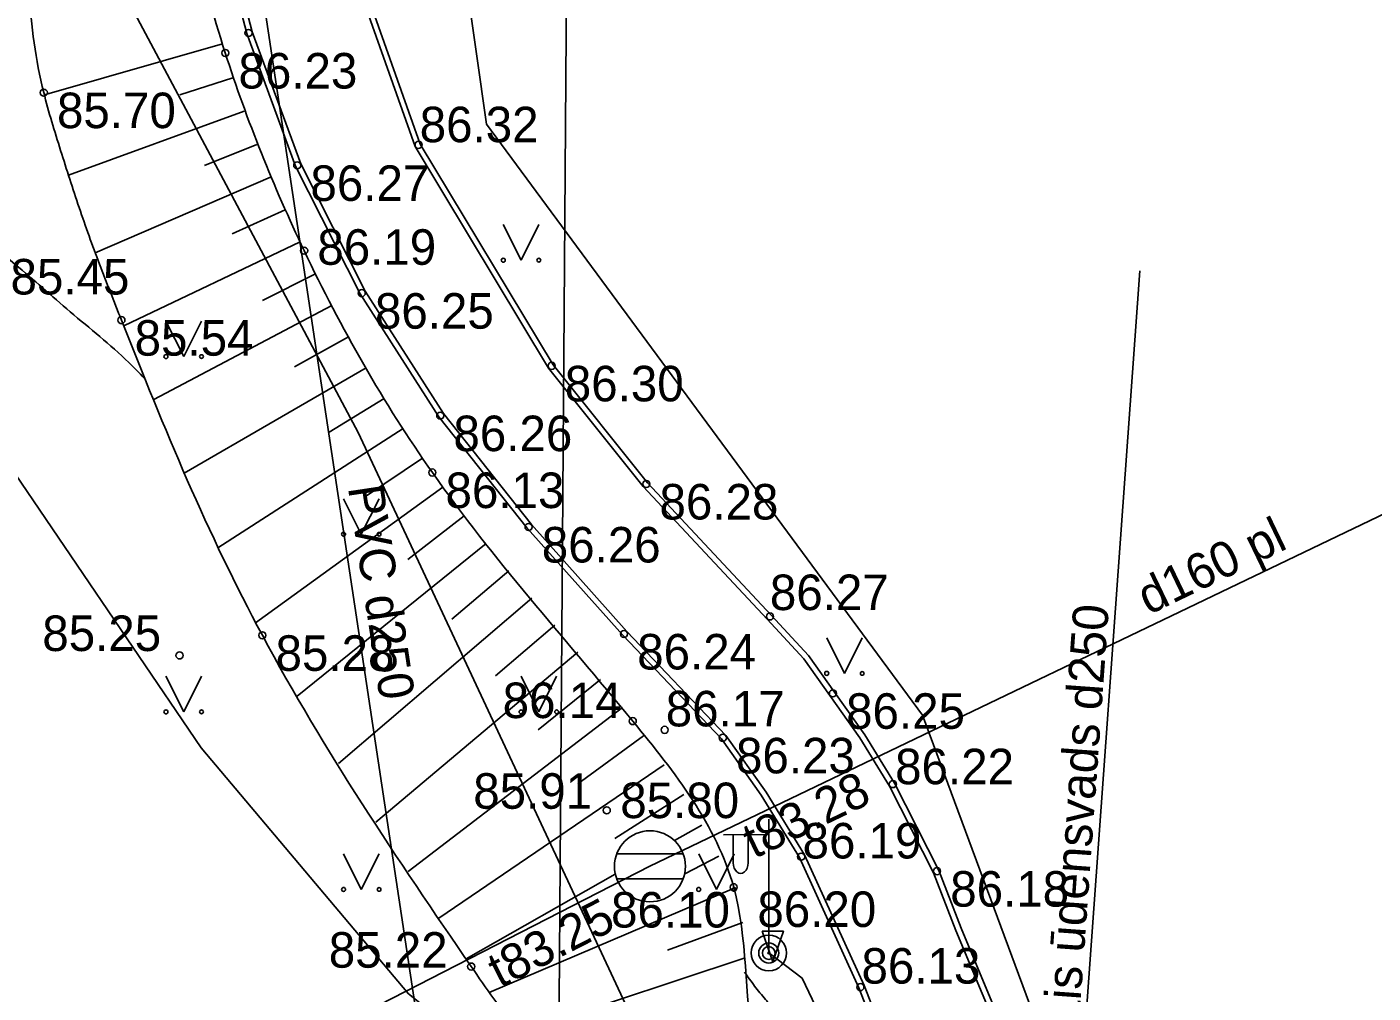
# Model space of a CAD drawing. Extents: x 576692 to 577659, y 273254 to 273799.
# Drawn here: x 576860.29 to 576879.24, y 273628.54 to 273642.14 of the extents above; entities that cross this region are included whole.
import ezdxf

# ---------------------------------------------------------------- set-up
doc = ezdxf.new("R2010")
doc.units = 0
for name, color, linetype in [('BUVE_EKAS_####_####_#', 7, 'Continuous'), ('CELI_TAKA_####_####_#', 7, 'Continuous'), ('GAZE_ELEM_####_####_#', 7, 'Continuous'), ('GEOD_ELEM_####_TKST_#', 7, 'Continuous'), ('GEOD_SITP_####_TKST_#', 7, 'Continuous'), ('HIDT_REZV_####_TKST_#', 7, 'Continuous'), ('Level 46', 7, 'Continuous'), ('Level 50', 7, 'Continuous'), ('LKAN_ELEM_####_####_#', 7, 'Continuous'), ('LKAN_ELEM_PAST_TKST_#', 7, 'Continuous'), ('RELJ_ELEM_####_####_#', 7, 'Continuous'), ('SAKK_KKAN_####_####_#', 7, 'Continuous'), ('SAKT_ACRL_####_####_#', 7, 'Continuous'), ('SAKT_ELEM_####_####_#', 7, 'Continuous'), ('SILT_VADP_DREN_TKST_#', 7, 'Continuous'), ('SILT_VADP_UDEN_####_#', 7, 'Continuous'), ('TERT_DIAM_####_TKST_#', 7, 'Continuous'), ('TERT_IZMT_####_TKST_#', 7, 'Continuous'), ('TERT_KONT_####_####_#', 7, 'Continuous'), ('TERT_KRND_####_####_#', 7, 'Continuous'), ('UDTK_VADP_UDEN_####_#', 7, 'Continuous')]:
    doc.layers.add(name, color=color, linetype=linetype)

msp = doc.modelspace()

# ---------------------------------------------------------------- linework, layer by layer
at = {"layer": 'BUVE_EKAS_####_####_#'}
for points in [[(576862.868, 273644.043), (576863.388, 273642.048), (576864.075, 273640.181), (576864.984, 273638.381), (576866.091, 273636.654), (576867.336, 273635.086), (576868.68, 273633.579), (576870.07, 273632.118), (576870.631, 273631.326), (576871.17, 273630.449), (576872.003, 273628.616), (576872.737, 273626.741), (576873.428, 273624.858), (576873.73, 273623.183), (576873.839, 273621.55), (576873.82, 273620.221), (576873.816, 273617.847)], [(576862.946, 273644.061), (576863.465, 273642.071), (576864.149, 273640.213), (576865.054, 273638.42), (576866.156, 273636.701), (576867.397, 273635.137), (576868.738, 273633.633), (576870.132, 273632.169), (576870.698, 273631.37), (576871.241, 273630.487), (576872.077, 273628.647), (576872.811, 273626.769), (576873.505, 273624.879), (576873.81, 273623.193), (576873.919, 273621.552), (576873.9, 273620.221), (576873.896, 273617.847)], [(576864.529, 273643.93), (576865.756, 273640.457), (576867.634, 273637.338), (576868.97, 273635.671), (576870.713, 273633.806), (576871.231, 273633.244), (576871.594, 273632.729), (576872.019, 273632.132), (576872.435, 273631.456), (576873.055, 273630.236), (576873.369, 273629.423), (576873.871, 273628.221), (576874.788, 273625.782), (576875.095, 273624.75), (576875.259, 273623.935), (576875.408, 273622.331), (576875.42, 273620.146), (576875.418, 273618.062), (576875.379, 273612.665)], [(576864.606, 273643.951), (576865.829, 273640.492), (576867.7, 273637.384), (576869.031, 273635.723), (576870.771, 273633.86), (576871.293, 273633.295), (576871.659, 273632.775), (576872.086, 273632.176), (576872.505, 273631.495), (576873.128, 273630.268), (576873.443, 273629.453), (576873.945, 273628.25), (576874.864, 273625.808), (576875.172, 273624.769), (576875.338, 273623.947), (576875.488, 273622.335), (576875.5, 273620.146), (576875.498, 273618.062), (576875.459, 273612.665)]]:
    msp.add_lwpolyline(points, dxfattribs=at)
at = {"layer": 'CELI_TAKA_####_####_#'}
msp.add_lwpolyline([(576822.461, 273734.186), (576841.308, 273671.168), (576850.453, 273673.856), (576864.919, 273653.745), (576866.76, 273640.771), (576872.899, 273632.451), (576876.069, 273623.909), (576875.901, 273608.92), (576873.238, 273590.115)], dxfattribs=at)
at = {"layer": 'GAZE_ELEM_####_####_#'}
for p, q in [((576863.048, 273641.904), (576860.538, 273641.186)), ((576863.191, 273641.425), (576862.443, 273641.185)), ((576863.353, 273640.952), (576860.877, 273640.052)), ((576863.531, 273640.484), (576862.79, 273640.19)), ((576863.723, 273640.023), (576861.254, 273638.961)), ((576863.926, 273639.566), (576863.184, 273639.227)), ((576864.137, 273639.113), (576861.656, 273637.932)), ((576864.355, 273638.663), (576863.608, 273638.29)), ((576864.583, 273638.217), (576862.077, 273636.896)), ((576864.82, 273637.777), (576864.061, 273637.358)), ((576865.066, 273637.342), (576862.508, 273635.86)), ((576865.322, 273636.912), (576864.547, 273636.438)), ((576865.587, 273636.489), (576862.978, 273634.81)), ((576865.862, 273636.071), (576865.071, 273635.54)), ((576866.147, 273635.66), (576863.51, 273633.755)), ((576866.446, 273635.259), (576865.655, 273634.646)), ((576866.757, 273634.868), (576864.099, 273632.721)), ((576867.075, 273634.483), (576866.272, 273633.806)), ((576867.399, 273634.101), (576864.677, 273631.774)), ((576867.724, 273633.721), (576866.891, 273633.009)), ((576868.047, 273633.34), (576865.206, 273630.946)), ((576868.366, 273632.954), (576867.488, 273632.245)), ((576868.676, 273632.562), (576865.659, 273630.253)), ((576868.974, 273632.161), (576868.048, 273631.485)), ((576869.263, 273631.753), (576866.093, 273629.598)), ((576869.538, 273631.335), (576868.568, 273630.719)), ((576869.796, 273630.907), (576869.408, 273630.687)), ((576870.034, 273630.468), (576869.552, 273630.22)), ((576868.575, 273630.215), (576866.475, 273629.024)), ((576870.248, 273630.016), (576866.801, 273628.55)), ((576870.37, 273629.533), (576869.312, 273629.146)), ((576870.389, 273629.034), (576867.22, 273627.984))]:
    msp.add_line(p, q, dxfattribs=at)
msp.add_spline([(576871.993, 273602.28), (576872.095, 273602.758), (576872.176, 273603.251), (576872.339, 273604.238), (576872.493, 273605.17), (576872.162, 273608.087), (576872.486, 273612.069), (576873.137, 273615.369), (576873.274, 273619.394), (576872.826, 273622.752), (576872.073, 273624.227), (576870.515, 273627.791), (576870.242, 273630.031), (576868.821, 273632.37), (576866, 273635.868), (576864.195, 273638.991), (576863.085, 273641.773), (576862.24, 273645.118), (576861.859, 273646.979)], degree=3, dxfattribs=at)
at = {"layer": 'GEOD_ELEM_####_TKST_#'}
msp.add_spline([(576870.76, 273628.369), (576870.69, 273628.451), (576870.537, 273628.64), (576870.395, 273628.836)], degree=3, dxfattribs=at)
at = {"layer": 'GEOD_SITP_####_TKST_#'}
for points in [[(576861.944, 273637.196), (576861.726, 273637.417), (576860.901, 273638.131), (576860.127, 273638.798), (576858.978, 273639.657), (576858.395, 273640.077), (576857.84, 273640.53), (576857.564, 273640.785), (576857.316, 273641.018), (576856.597, 273641.49), (576856.2, 273641.67), (576855.798, 273641.837), (576855.593, 273641.907), (576855.382, 273641.961), (576855.173, 273642.017), (576854.971, 273642.095), (576854.43, 273642.415), (576853.964, 273642.77), (576853.807, 273642.89), (576853.719, 273642.985), (576853.606, 273643.166), (576853.406, 273643.456), (576852.886, 273644.111), (576852.33, 273644.736), (576851.768, 273645.358), (576851.229, 273646.003), (576850.524, 273647.121), (576849.856, 273649.094), (576849.566, 273649.945), (576849.363, 273650.71), (576849.197, 273651.566), (576849.122, 273651.997), (576849.027, 273652.425), (576848.722, 273653.106), (576848.503, 273653.417), (576848.252, 273653.711), (576847.538, 273654.384), (576846.74, 273654.934), (576846.125, 273655.24), (576845.589, 273655.423), (576845.052, 273655.599), (576844.514, 273655.774), (576843.979, 273655.956), (576840.467, 273657.219), (576839.349, 273657.676), (576838.036, 273658.288), (576837.017, 273658.817), (576836.521, 273659.108), (576836.035, 273659.42), (576835.446, 273659.937), (576833.078, 273662.646), (576832.622, 273663.212), (576832.525, 273663.418)], [(576836.737, 273653.507), (576837.199, 273653.071), (576838.168, 273651.964), (576839.276, 273650.389), (576839.675, 273649.775), (576840.068, 273649.157), (576840.874, 273647.935), (576842.937, 273645.043), (576843.644, 273644.077), (576844.358, 273643.116), (576845.071, 273642.154), (576845.776, 273641.185), (576846.532, 273639.939), (576848.959, 273635.068), (576849.467, 273633.911), (576849.494, 273633.87), (576849.54, 273633.844), (576849.669, 273633.76), (576849.716, 273633.696), (576849.75, 273633.628), (576849.789, 273633.484), (576849.818, 273633.184), (576849.885, 273632.56), (576849.923, 273631.934), (576849.964, 273631.308), (576850.042, 273630.684), (576850.228, 273630.011), (576850.401, 273629.706), (576850.514, 273629.568), (576850.649, 273629.442), (576850.839, 273629.33), (576851.04, 273629.256), (576851.437, 273629.127), (576852.241, 273628.927), (576852.405, 273628.885), (576852.774, 273628.757), (576853.14, 273628.623), (576853.871, 273628.35), (576855.336, 273627.811), (576856.838, 273627.284), (576857.811, 273626.95), (576859.757, 273626.119), (576860.71, 273625.654), (576861.662, 273625.19), (576862.208, 273624.916), (576862.747, 273624.63), (576863.288, 273624.343), (576863.84, 273624.071), (576864.734, 273623.812), (576865.684, 273623.739), (576866.647, 273623.686), (576867.118, 273623.618), (576867.35, 273623.56), (576867.582, 273623.491), (576867.793, 273623.35), (576869.286, 273620.101), (576869.949, 273618.673), (576870.065, 273618.383)]]:
    msp.add_spline(points, degree=3, dxfattribs=at)
at = {"layer": 'Level 46'}
msp.add_lwpolyline([(576819.084, 273508.06), (576836.748, 273524.115), (576867.586, 273601.172), (576868.039, 273663.467), (576868.105, 273672.497), (576868.105, 273672.497)], dxfattribs=at)
at = {"layer": 'Level 50'}
msp.add_lwpolyline([(576852.738, 273621.958), (576869.063, 273630.326), (576880.368, 273635.749)], dxfattribs=at)
at = {"layer": 'LKAN_ELEM_####_####_#'}
msp.add_lwpolyline([(576866.359, 273669.976), (576862.144, 273665.514), (576859.774, 273661.295), (576857.536, 273656.168), (576856.942, 273651.163), (576856.77, 273646.273), (576858.075, 273640.911), (576859.856, 273636.242), (576862.744, 273631.994), (576865.665, 273628.533), (576869.677, 273625.341)], dxfattribs=at)
at = {"layer": 'LKAN_ELEM_PAST_TKST_#'}
for p, q in [((576866.999, 273639.357), (576867.249, 273638.857)), ((576867.249, 273638.857), (576867.499, 273639.357)), ((576862.25, 273638), (576862.5, 273637.5)), ((576862.5, 273637.5), (576862.75, 273638)), ((576864.75, 273635.5), (576865, 273635)), ((576865, 273635), (576865.25, 273635.5)), ((576871.553, 273633.541), (576871.803, 273633.041)), ((576871.803, 273633.041), (576872.053, 273633.541)), ((576862.25, 273633), (576862.5, 273632.5)), ((576862.5, 273632.5), (576862.75, 273633)), ((576867.25, 273633), (576867.5, 273632.5)), ((576867.5, 273632.5), (576867.75, 273633)), ((576864.75, 273630.5), (576865, 273630)), ((576865, 273630), (576865.25, 273630.5)), ((576869.75, 273630.5), (576870, 273630)), ((576870, 273630), (576870.25, 273630.5))]:
    msp.add_line(p, q, dxfattribs=at)
for centre, radius in [((576866.999, 273638.857), 0.028), ((576867.499, 273638.857), 0.0263), ((576862.25, 273637.5), 0.028), ((576862.75, 273637.5), 0.0263), ((576864.75, 273635), 0.028), ((576865.25, 273635), 0.0263), ((576871.552, 273633.041), 0.028), ((576872.052, 273633.041), 0.0263), ((576862.25, 273632.5), 0.028), ((576862.75, 273632.5), 0.0263), ((576867.25, 273632.5), 0.028), ((576867.75, 273632.5), 0.0263), ((576864.75, 273630), 0.028), ((576865.25, 273630), 0.0263), ((576869.75, 273630), 0.028), ((576870.25, 273630), 0.0263)]:
    msp.add_circle(centre, radius, dxfattribs=at)
at = {"layer": 'RELJ_ELEM_####_####_#'}
msp.add_lwpolyline([(576870.643, 273629.413), (576870.943, 273629.413), (576870.793, 273628.98)], close=True, dxfattribs=at)
for centre in [(576863.412, 273642.055), (576863.085, 273641.773), (576860.53, 273641.215), (576865.806, 273640.481), (576864.098, 273640.191), (576864.195, 273638.991), (576865.006, 273638.393), (576861.623, 273638.013), (576867.679, 273637.37), (576866.111, 273636.669), (576866, 273635.868), (576869.012, 273635.707), (576867.355, 273635.102), (576870.753, 273633.843), (576863.607, 273633.577), (576868.698, 273633.596), (576862.441, 273633.294), (576871.639, 273632.761), (576868.821, 273632.37), (576869.27, 273632.246), (576870.089, 273632.134), (576872.483, 273631.483), (576868.455, 273631.114), (576871.192, 273630.461), (576873.105, 273630.258), (576870.242, 273630.031), (576866.547, 273628.915), (576872.026, 273628.626)]:
    msp.add_circle(centre, 0.05, dxfattribs=at)
at = {"layer": 'SAKT_ACRL_####_####_#'}
for points in [[(576861.136, 273668.467), (576860.963, 273659.027), (576862.791, 273648.045), (576864.507, 273636.663), (576866.223, 273625.281), (576874.841, 273626.049), (576875.066, 273626.068)], [(576875.075, 273626.417), (576875.958, 273638.708)]]:
    msp.add_lwpolyline(points, dxfattribs=at)
at = {"layer": 'SAKT_ELEM_####_####_#'}
msp.add_spline([(576861.859, 273646.979), (576860.82, 273645.526), (576860.515, 273644.822), (576860.439, 273644.436), (576860.391, 273644.05), (576860.328, 273642.626), (576860.53, 273641.215), (576860.767, 273640.401), (576861.028, 273639.597), (576861.313, 273638.803), (576861.623, 273638.013), (576862.55, 273635.763), (576863.607, 273633.577), (576866.547, 273628.915), (576866.865, 273628.461), (576867.195, 273628.017), (576867.524, 273627.57), (576867.837, 273627.109), (576868.459, 273625.886), (576868.71, 273625.244), (576868.949, 273624.589), (576869.329, 273623.47), (576869.651, 273622.345), (576869.905, 273621.213), (576870.003, 273620.644), (576870.079, 273620.073), (576870.081, 273618.528), (576869.968, 273617.754), (576869.793, 273616.99), (576869.618, 273616.466), (576869.409, 273615.957), (576869.202, 273615.447), (576869.037, 273614.924), (576868.882, 273614.274), (576868.742, 273613.621), (576868.549, 273612.302), (576868.479, 273611.255), (576868.436, 273610.206), (576868.398, 273609.158), (576868.341, 273608.112), (576868.191, 273607.038), (576867.976, 273605.964), (576867.823, 273604.893), (576867.861, 273603.826), (576868.001, 273602.973)], degree=3, dxfattribs=at)
at = {"layer": 'SILT_VADP_UDEN_####_#'}
msp.add_lwpolyline([(576868.105, 273672.497), (576868.039, 273663.467), (576867.586, 273601.172), (576836.748, 273524.115), (576819.084, 273508.06)], dxfattribs=at)
at = {"layer": 'TERT_DIAM_####_TKST_#'}
for p, q in [((576870.736, 273629.106), (576870.736, 273630.989)), ((576870.736, 273630.773), (576870.101, 273630.768)), ((576870.236, 273630.769), (576870.236, 273630.377)), ((576870.446, 273630.771), (576870.446, 273630.377))]:
    msp.add_line(p, q, dxfattribs=at)
for radius in [0.25, 0.09]:
    msp.add_circle((576870.736, 273629.106), radius, dxfattribs=at)
msp.add_ellipse((576870.341, 273630.377), major_axis=(0, 0.151), ratio=0.695971, start_param=1.570796, end_param=4.712389, dxfattribs=at)
at = {"layer": 'TERT_KONT_####_####_#'}
for radius in [0.141, 0.0126]:
    msp.add_circle((576870.736, 273629.106), radius, dxfattribs=at)
at = {"layer": 'TERT_KRND_####_####_#'}
for points in [[(576872.377, 273604.118), (576872.656, 273614.414), (576871.639, 273621.034), (576869.298, 273627.151), (576864.957, 273636.431), (576861.433, 273643.047), (576860.673, 273648.367), (576862.425, 273654.978)], [(576872.377, 273604.118), (576872.717, 273605.326), (576873.157, 273607.482), (576873.609, 273611.716), (576873.631, 273615.791), (576873.747, 273621.641), (576873.103, 273624.769), (576871.205, 273628.75), (576870.736, 273629.106)]]:
    msp.add_lwpolyline(points, dxfattribs=at)
at = {"layer": 'UDTK_VADP_UDEN_####_#'}
for p, q in [((576868.595, 273630.501), (576869.531, 273630.501)), ((576868.595, 273630.151), (576869.531, 273630.151))]:
    msp.add_line(p, q, dxfattribs=at)
msp.add_circle((576869.063, 273630.326), 0.5, dxfattribs=at)

# ---------------------------------------------------------------- texts
at = {"layer": 'HIDT_REZV_####_TKST_#'}
for s, p in [(' 86.23', (576863.085, 273641.273)), (' 85.70', (576860.53, 273640.715)), (' 86.32', (576865.636, 273640.517)), (' 86.27', (576864.098, 273639.691)), (' 86.19', (576864.195, 273638.792)), (' 85.45', (576859.876, 273638.374)), (' 86.25', (576865.006, 273637.893)), (' 85.54', (576861.623, 273637.513)), (' 86.30', (576867.679, 273636.87)), (' 86.26', (576866.111, 273636.169)), (' 86.13', (576866, 273635.368)), (' 86.28', (576869.012, 273635.207)), (' 86.26', (576867.355, 273634.602)), (' 86.27', (576870.566, 273633.932)), (' 85.25', (576860.323, 273633.356)), (' 85.28', (576863.607, 273633.077)), (' 86.24', (576868.698, 273633.096)), (' 86.14', (576866.804, 273632.412)), (' 86.17', (576869.1, 273632.295)), (' 86.25', (576871.639, 273632.261)), (' 86.23', (576870.089, 273631.634)), (' 86.22', (576872.329, 273631.481)), (' 85.91', (576866.39, 273631.136)), (' 86.19', (576871.026, 273630.436)), (' 86.18', (576873.105, 273629.758)), (' 86.10', (576868.33, 273629.464)), (' 86.20', (576870.39, 273629.472)), (' 85.22', (576864.356, 273628.899)), (' 86.13', (576871.856, 273628.675))]:
    msp.add_text(s, height=0.5, dxfattribs=at).set_placement(p)
at = {"layer": 'SAKK_KKAN_####_####_#'}
msp.add_text('  85.80', height=0.5, dxfattribs=at).set_placement((576868.274, 273631.004))
at = {"layer": 'SILT_VADP_DREN_TKST_#'}
for s, rotation, p in [('PVC d250', 278.5736, (576864.81, 273635.659)), ('vecais ūdensvads d250', 85.8909, (576875.025, 273627.026))]:
    msp.add_text(s, height=0.5, rotation=rotation, dxfattribs=at).set_placement(p)
at = {"layer": 'TERT_IZMT_####_TKST_#'}
for s, rotation, p in [('d160 pl', 25.6265, (576876.082, 273633.859)), ('t83.28', 25.6265, (576870.529, 273630.426)), ('t83.25', 27.1385, (576866.953, 273628.606))]:
    msp.add_text(s, height=0.5, rotation=rotation, dxfattribs=at).set_placement(p)

doc.saveas('drawing.dxf')
